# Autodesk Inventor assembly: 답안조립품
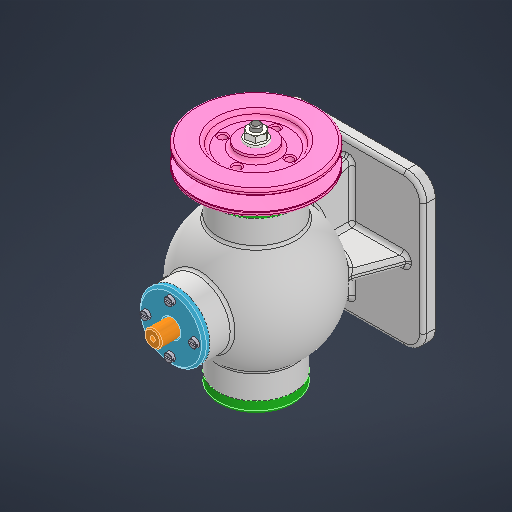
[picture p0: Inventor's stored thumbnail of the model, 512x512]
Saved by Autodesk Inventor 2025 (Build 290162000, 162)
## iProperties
Created: 2025-08
Part Number: 답안조립품
Document SubType Name: Assembly
Designer: infra006
Author: infra006
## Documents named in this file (15)
- C:\Users\infra006\Desktop\750807V1001\답안조립품.iam
- C:\Users\infra006\Desktop\750807V1001\본체.ipt
- C:\Users\infra006\Desktop\750807V1001\슬라이드\슬라이드.ipt
- C:\Users\infra006\Desktop\750807V1001\볼트 M4 x 12\볼트 M4 x 12.ipt
- C:\Users\infra006\Desktop\750807V1001\볼트 M4 x 16\볼트 M4 x 16.ipt
- C:\Users\infra006\Desktop\750807V1001\너트 M8\너트 M8.ipt
- C:\Users\infra006\Desktop\750807V1001\V-벨트풀리\V-벨트풀리.ipt
- C:\Users\infra006\Desktop\750807V1001\오일실 15 30 7\오일실 15 30 7.ipt
- C:\Users\infra006\Desktop\750807V1001\키 4 x 4 x 12\키 4 x 4 x 12.ipt
- C:\Users\infra006\Desktop\750807V1001\편심축\편심축.ipt
- C:\Users\infra006\Desktop\750807V1001\칼라\칼라.ipt
- C:\Users\infra006\Desktop\750807V1001\베어링- 6202\베어링- 6202.ipt
- C:\Users\infra006\Desktop\750807V1001\상부커버\상부커버.ipt
- C:\Users\infra006\Desktop\750807V1001\앞커버\앞커버.ipt
- C:\Users\infra006\Desktop\750807V1001\뒤커버\뒤커버.ipt
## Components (1 placed, 1 different names)
1. V-벨트풀리:1
